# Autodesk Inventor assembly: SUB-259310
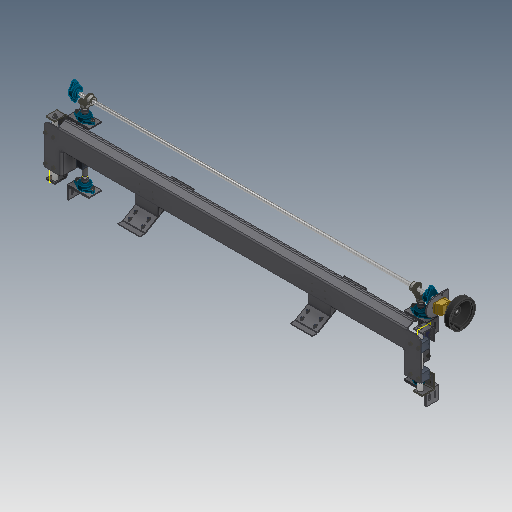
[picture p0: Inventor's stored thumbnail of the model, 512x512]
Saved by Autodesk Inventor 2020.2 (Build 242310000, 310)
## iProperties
Created: 2000-02
Part Number: SUB-259310
Document SubType Name: Assembly
Designer: sspink
Mass: 24162.7 g
Surface Area: 20552 cm^2
Volume: 6313.71 cm^3
Density: 3.82701 g/cm^3
Control State: 0
Checked Out: False
Master: False
Shininess: 0.0
Length Units: 11269
Angle Units: 11279
Time Units: 11290
Mass Units: 11283
Length Display Precision: 3
Angle Display Precision: 2
Compacted: True
Dimensions: 609,1x346,8x2359,6 mm
Mass: 24,163 kg
DocNumber: SUB-259310.iam
Folder: 01 - Themengebiete\Simplification\01 - Packaging machine\
VDS_Category: 3D Komponenten
Density: 0.0
Volumn: 0.0
Area: 0.0
PropertySet Name: Model Information
Author: sspink
Revision Number: -
Title: SUB-259310
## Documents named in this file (35)
- D:\07 - DEMODATEN\OTX 2019 - Dataset - UPDATE - Dez2019\Designs\07-Packing machine\SUB-259310.iam
- D:\07 - DEMODATEN\OTX 2019 - Dataset - UPDATE - Dez2019\Designs\07-Packing machine\Parts\ADSK-011691.ipt
- D:\07 - DEMODATEN\OTX 2019 - Dataset - UPDATE - Dez2019\Designs\07-Packing machine\Parts\ADSK-011692.ipt
- D:\07 - DEMODATEN\OTX 2019 - Dataset - UPDATE - Dez2019\Designs\07-Packing machine\Parts\ADSK-011325.ipt
- D:\07 - DEMODATEN\OTX 2019 - Dataset - UPDATE - Dez2019\Designs\07-Packing machine\Parts\ADSK-011690.ipt
- D:\07 - DEMODATEN\OTX 2019 - Dataset - UPDATE - Dez2019\Designs\07-Packing machine\Parts\ADSK-011695.ipt
- D:\07 - DEMODATEN\OTX 2019 - Dataset - UPDATE - Dez2019\Designs\07-Packing machine\Parts\ADSK-011694.ipt
- D:\07 - DEMODATEN\OTX 2019 - Dataset - UPDATE - Dez2019\Designs\07-Packing machine\500738.iam
- D:\07 - DEMODATEN\OTX 2019 - Dataset - UPDATE - Dez2019\Designs\07-Packing machine\Parts\ADSK-011697.ipt
- D:\07 - DEMODATEN\OTX 2019 - Dataset - UPDATE - Dez2019\Designs\07-Packing machine\500745.iam
- D:\07 - DEMODATEN\OTX 2019 - Dataset - UPDATE - Dez2019\Designs\07-Packing machine\Parts\ADSK-011714.ipt
- D:\07 - DEMODATEN\OTX 2019 - Dataset - UPDATE - Dez2019\Designs\07-Packing machine\Parts\ADSK-011700.ipt
- D:\07 - DEMODATEN\OTX 2019 - Dataset - UPDATE - Dez2019\Designs\07-Packing machine\Parts\ADSK-011716.ipt
- D:\07 - DEMODATEN\OTX 2019 - Dataset - UPDATE - Dez2019\Designs\07-Packing machine\Parts\ADSK-011702.ipt
- D:\07 - DEMODATEN\OTX 2019 - Dataset - UPDATE - Dez2019\Designs\07-Packing machine\Parts\ADSK-011309.ipt
- D:\07 - DEMODATEN\OTX 2019 - Dataset - UPDATE - Dez2019\Designs\07-Packing machine\Parts\ADSK-011704.ipt
- D:\07 - DEMODATEN\OTX 2019 - Dataset - UPDATE - Dez2019\Designs\07-Packing machine\Parts\ADSK-011768.ipt
- D:\07 - DEMODATEN\OTX 2019 - Dataset - UPDATE - Dez2019\Content Center Files\de-DE\DIN 125-1  B\DIN 125-1 - B 6,4.ipt
- D:\07 - DEMODATEN\OTX 2019 - Dataset - UPDATE - Dez2019\Content Center Files\de-DE\ISO 4032(1)\ISO 4032 - M6DIN EN.ipt
- D:\07 - DEMODATEN\OTX 2019 - Dataset - UPDATE - Dez2019\Content Center Files\de-DE\DIN 125-1  B\DIN 125-1 - B 5,3.ipt
- D:\07 - DEMODATEN\OTX 2019 - Dataset - UPDATE - Dez2019\Content Center Files\de-DE\ISO 4762(2)\ISO 4762 - M5 x 10ISO.ipt
- D:\07 - DEMODATEN\OTX 2019 - Dataset - UPDATE - Dez2019\Content Center Files\de-DE\DIN 125-1  B\DIN 125-1 - B 8,4.ipt
- D:\07 - DEMODATEN\OTX 2019 - Dataset - UPDATE - Dez2019\Content Center Files\de-DE\ISO 4032(1)\ISO 4032 - M8DIN EN.ipt
- D:\07 - DEMODATEN\OTX 2019 - Dataset - UPDATE - Dez2019\Content Center Files\de-DE\ISO 4762(2)\ISO 4762 - M8 x 55ISO.ipt
- D:\07 - DEMODATEN\OTX 2019 - Dataset - UPDATE - Dez2019\Content Center Files\de-DE\DIN 125-1  B\DIN 125-1 - B 10,5.ipt
- D:\07 - DEMODATEN\OTX 2019 - Dataset - UPDATE - Dez2019\Content Center Files\de-DE\ISO 4762(2)\ISO 4762 - M10 x 25ISO.ipt
- D:\07 - DEMODATEN\OTX 2019 - Dataset - UPDATE - Dez2019\Content Center Files\de-DE\ISO 4762(2)\ISO 4762 - M8 x 40ISO.ipt
- D:\07 - DEMODATEN\OTX 2019 - Dataset - UPDATE - Dez2019\Content Center Files\de-DE\ISO 2491 - A\ISO 2491 - A  5 x 3 x 16.ipt
- D:\07 - DEMODATEN\OTX 2019 - Dataset - UPDATE - Dez2019\Content Center Files\de-DE\ISO 4026\ISO 4026 - M5 x 6 - ISO.ipt
- D:\07 - DEMODATEN\OTX 2019 - Dataset - UPDATE - Dez2019\Content Center Files\de-DE\ISO 4026\ISO 4026 - M5 x 10 - ISO.ipt
- D:\07 - DEMODATEN\OTX 2019 - Dataset - UPDATE - Dez2019\Content Center Files\de-DE\ISO 4762(2)\ISO 4762 - M8 x 25ISO.ipt
- D:\07 - DEMODATEN\OTX 2019 - Dataset - UPDATE - Dez2019\Content Center Files\de-DE\ISO 4026\ISO 4026 - M5 x 8 - ISO.ipt
- D:\07 - DEMODATEN\OTX 2019 - Dataset - UPDATE - Dez2019\Designs\07-Packing machine\Parts\ADSK-014457.ipt
- D:\07 - DEMODATEN\OTX 2019 - Dataset - UPDATE - Dez2019\Content Center Files\de-DE\ISO 2491 - A\ISO 2491 - A  5 x 3 x 28.ipt
- D:\07 - DEMODATEN\OTX 2019 - Dataset - UPDATE - Dez2019\Content Center Files\de-DE\ISO 2491 - A\ISO 2491 - A  5 x 3 x 36.ipt
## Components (146 placed, 34 different names)
1. ADSK-011714:1 — Passend:163, Passend:164, Passend:170, Fluchtend:172, Passend:218
2. ADSK-011694:1 — Angle:2, Passend:45, Passend:46, Passend:47, Passend:48, Passend:49, Passend:50, Passend:107, Passend:108, Passend:109, Passend:110, Passend:111, Passend:112, Passend:113, Passend:114, Passend:115, Passend:116, Passend:117, Passend:118, Passend:135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
3. ADSK-011695:2 — Passend:45, Passend:48, Passend:49, Passend:51, Passend:53, Passend:54, Passend:55, Passend:68, Passend:70, Passend:72, Passend:74, Passend:76, Passend:78, Passend:80, Passend:82, Passend:84, Passend:86, Passend:88, Passend:90
4. ADSK-011695:1 — Passend:46, Passend:47, Passend:50, Passend:52, Passend:56, Passend:57, Passend:58, Passend:60, Passend:62, Passend:64, Passend:66
5. 500738:2 [sub-assembly] — Passend:51, Passend:53, Passend:54, Passend:55
6. 500738:1 [sub-assembly] — Passend:52, Passend:56, Passend:57, Passend:58
7. ADSK-011325:1 — Passend:113, Passend:114, Passend:115, Passend:123, Fluchtend:23, Passend:124, Passend:125
8. ADSK-011325:2 — Passend:116, Passend:117, Passend:118, Fluchtend:24
9. ADSK-011325:3 — Passend:110, Passend:111, Passend:112, Passend:121
10. ADSK-011325:4 — Passend:107, Passend:108, Passend:109, Passend:119, Passend:120
11. ADSK-011692:1 — Passend:125, Passend:126, Einfügen:50
12. ADSK-011692:2 — Passend:121, Passend:122, Einfügen:49
13. ADSK-011690:1 — Angle:2, Mate:25, Einfügen:49, Passend:134
14. ADSK-011690:2 — Passend:123, Fluchtend:23, Passend:124, Passend:126, Passend:130
15. ADSK-011691:1 — Einfügen:50, Fluchtend:24, Passend:128, Fluchtend:32
16. ADSK-011691:2 — Passend:119, Passend:120, Passend:122, Passend:132
17. ADSK-011697:1 — Passend:135, Passend:136, Passend:137, Passend:156, Drehung/Translation:1
18. ADSK-011714:2 — Mate:24, Mate:25, Passend:170, Passend:217
19. 500745:1 [sub-assembly] — Passend:147, Passend:148, Passend:162, Passend:225, Passend:226, Passend:233, Passend:234, Fluchtend:175, Passend:235, Tangential:6
20. ADSK-011700:1 — Mate:24, Mate:41, Mate:42, Passend:164, Fluchtend:34, Passend:166, Fluchtend:168, Passend:167, Passend:169, Tangential:2, Passend:221, Passend:222, Passend:224, Passend:227, Passend:229, Passend:236, Fluchtend:176, Passend:237, Passend:238, Passend:239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
21. ADSK-011714:4 — Passend:144, Passend:145, Passend:146, Passend:147, Passend:148, Passend:217
22. ADSK-011702:2 — Fluchtend:25, Fluchtend:26, Fluchtend:27, Passend:144, Passend:145, Passend:146
23. ADSK-011714:6 — Insert:12, Mate:39, Passend:142, Passend:143
24. ADSK-011702:4 — Insert:12, EINSTELLUNG, Passend:143, Fluchtend:25, Fluchtend:26, Fluchtend:27, Winkel:11, Fluchtend:31, Passend:157
25. ADSK-011716:2 — Mate:39, Passend:162
26. ADSK-011309:1 — Mate:44, Fluchtend:34, Passend:166, Fluchtend:168, Passend:177, Passend:178
27. ADSK-011768:1 — Mate:42, Mate:43, Angle:10, Mate:44, Fluchtend:173
28. ADSK-011704:1 — Mate:41, Mate:43, Angle:10, Fluchtend:32, Passend:163, Fluchtend:172, Fluchtend:173
29. ADSK-011697:2 — Passend:138, Passend:139, Passend:140, EINSTELLUNG, Passend:142
30. 500745:2 [sub-assembly] — Passend:156, Passend:161, Passend:220, Passend:223, Passend:228, Passend:231, Passend:232, Fluchtend:174, Tangential:4, Drehung/Translation:1
31. ADSK-011714:7
32. ADSK-011702:5 — Passend:218
33. ADSK-011714:8 — Passend:198, Passend:200
34. ADSK-011702:6 — Fluchtend:31, Passend:157
35. ADSK-011716:3 — Passend:161
36. Kegelrad1:3 — Passend:220, Passend:222, Passend:228, Passend:246, Passend:247, Drehung:1
37. Kegelrad1:4 — Passend:221, Passend:223, Fluchtend:176, Passend:243, Passend:245, Drehung:1
38. Kegelrad1:5 — Passend:226, Passend:227, Passend:235, Passend:252, Passend:254, Drehung:2
39. Kegelrad1:6 — Passend:224, Passend:225, Passend:236, Passend:249, Passend:251, Drehung:2
40. ISO 2491 A A  5 x 3 x 28:1 — Passend:231, Passend:232, Fluchtend:174, Passend:248
41. ISO 2491 A A  5 x 3 x 28:2 — Passend:233, Passend:234, Fluchtend:175, Passend:253
42. ISO 2491 A A  5 x 3 x 36:1 — Passend:237, Passend:238, Passend:239, Passend:244
43. ISO 2491 A A  5 x 3 x 36:2 — Passend:240, Passend:241, Passend:242, Passend:250
44. ISO 4026 M5 x 10:2 — Passend:246, Tangential:4
45. ISO 4026 M5 x 8:7 — Passend:247, Passend:248
46. ISO 4026 M5 x 10:3 — Passend:249, Passend:250
47. ISO 4026 M5 x 10:4 — Passend:251, Tangential:5
48. ISO 4026 M5 x 10:5 — Passend:252, Passend:253
49. ISO 4026 M5 x 10:6 — Passend:254, Tangential:6
50. ISO 4026 M5 x 10:1 — Passend:245, Tangential:3
51. ISO 4026 M5 x 8:6 — Passend:243, Passend:244
52. DIN 125-1 B B 8,4:13 — Passend:210, Passend:212
53. DIN 125-1 B B 8,4:14
54. DIN 125-1 B B 8,4:15 — Passend:214, Passend:216
55. DIN 125-1 B B 8,4:16
56. DIN 125-1 B B 8,4:17 — Passend:198, Passend:206, Passend:208
57. DIN 125-1 B B 8,4:18 — Passend:200
58. DIN 125-1 B B 8,4:19 — Passend:202, Passend:204
59. DIN 125-1 B B 8,4:20
60. ISO 4762 M8 x 25:1 — Passend:202
61. ISO 4762 M8 x 25:2 — Passend:204
62. ISO 4762 M8 x 25:3 — Passend:206
63. ISO 4762 M8 x 25:4 — Passend:208
64. ISO 4762 M8 x 25:5 — Passend:210
65. ISO 4762 M8 x 25:6 — Passend:212
66. ISO 4762 M8 x 25:7 — Passend:214
67. ISO 4762 M8 x 25:8 — Passend:216
68. ISO 2491 A A  5 x 3 x 16:1 — Passend:167, Passend:169, Passend:229, Passend:230
69. ISO 4026 M5 x 6:1 — Passend:178, Passend:230
70. ISO 4026 M5 x 6:2 — Passend:177, Tangential:2
71. DIN 125-1 B B 10,5:1 — Passend:128
72. DIN 125-1 B B 10,5:2 — Passend:130
73. DIN 125-1 B B 10,5:3 — Passend:132
74. DIN 125-1 B B 10,5:4 — Passend:134
75. ISO 4762 M10 x 25:1
76. ISO 4762 M10 x 25:2
77. ISO 4762 M10 x 25:3
78. ISO 4762 M10 x 25:4
79. DIN 125-1 B B 8,4:9
80. DIN 125-1 B B 8,4:10
81. DIN 125-1 B B 8,4:11
82. DIN 125-1 B B 8,4:12
83. DIN EN 24032 M8:9
84. DIN EN 24032 M8:10
85. DIN EN 24032 M8:11
86. DIN EN 24032 M8:12
87. ISO 4762 M8 x 40:1
88. ISO 4762 M8 x 40:2
89. ISO 4762 M8 x 40:3
90. ISO 4762 M8 x 40:4
91. DIN 125-1 B B 8,4:1
92. DIN 125-1 B B 8,4:2
93. DIN 125-1 B B 8,4:3
94. DIN 125-1 B B 8,4:4
95. DIN 125-1 B B 8,4:5
96. DIN 125-1 B B 8,4:6
97. DIN 125-1 B B 8,4:7
98. DIN 125-1 B B 8,4:8
99. DIN EN 24032 M8:1
100. DIN EN 24032 M8:2
101. DIN EN 24032 M8:3
102. DIN EN 24032 M8:4
103. DIN EN 24032 M8:5
104. DIN EN 24032 M8:6
105. DIN EN 24032 M8:7
106. DIN EN 24032 M8:8
107. ISO 4762 M8 x 55:1
108. ISO 4762 M8 x 55:2
109. ISO 4762 M8 x 55:3
110. ISO 4762 M8 x 55:4
111. ISO 4762 M8 x 55:5
112. ISO 4762 M8 x 55:6
113. ISO 4762 M8 x 55:7
114. ISO 4762 M8 x 55:8
115. DIN 125-1 B B 6,4:1 — Passend:60
116. DIN 125-1 B B 6,4:2 — Passend:62
117. DIN 125-1 B B 6,4:3 — Passend:64
118. DIN 125-1 B B 6,4:4 — Passend:66
119. DIN EN 24032 M6:1
120. DIN EN 24032 M6:2
121. DIN EN 24032 M6:3
122. DIN EN 24032 M6:4
123. DIN 125-1 B B 6,4:5 — Passend:68
124. DIN 125-1 B B 6,4:6 — Passend:70
125. DIN 125-1 B B 6,4:7 — Passend:72
126. DIN 125-1 B B 6,4:8 — Passend:74
127. DIN EN 24032 M6:5
128. DIN EN 24032 M6:6
129. DIN EN 24032 M6:7
130. DIN EN 24032 M6:8
131. DIN 125-1 B B 5,3:1 — Passend:76
132. DIN 125-1 B B 5,3:2 — Passend:78
133. DIN 125-1 B B 5,3:3 — Passend:80
134. DIN 125-1 B B 5,3:4 — Passend:82, Passend:92, Passend:94, Passend:96, Passend:98, Passend:100, Passend:102, Passend:104, Passend:106
135. DIN 125-1 B B 5,3:5 — Passend:84
136. DIN 125-1 B B 5,3:6 — Passend:86
137. DIN 125-1 B B 5,3:7 — Passend:88
138. DIN 125-1 B B 5,3:8 — Passend:90
139. ISO 4762 M5 x 10:1 — Passend:92
140. ISO 4762 M5 x 10:2 — Passend:94
141. ISO 4762 M5 x 10:3 — Passend:96
142. ISO 4762 M5 x 10:4 — Passend:98
143. ISO 4762 M5 x 10:5 — Passend:100
144. ISO 4762 M5 x 10:6 — Passend:102
145. ISO 4762 M5 x 10:7 — Passend:104
146. ISO 4762 M5 x 10:8 — Passend:106
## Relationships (170: Mate 142, Flush 14, Tangent 5, Angle 3, Insert 3, RelateRotation 2, RelateRotateTranslate 1)
- EINSTELLUNG [Mate]: ADSK-011702:4 ↔ ADSK-011697:2
- Drehung/Translation:1 [RelateRotateTranslate]: ADSK-011697:1 ↔ 500745:2
- Angle:2: ADSK-011694:1 ↔ ADSK-011690:1
- Mate:24: ADSK-011714:2 ↔ ADSK-011700:1
- Mate:25: ADSK-011690:1 ↔ ADSK-011714:2
- Insert:12: ADSK-011714:6 ↔ ADSK-011702:4
- Mate:39: ADSK-011714:6 ↔ ADSK-011716:2
- Mate:41: ADSK-011700:1 ↔ ADSK-011704:1
- Mate:42: ADSK-011700:1 ↔ ADSK-011768:1
- Mate:43: ADSK-011768:1 ↔ ADSK-011704:1
- Angle:10: ADSK-011768:1 ↔ ADSK-011704:1
- Mate:44: ADSK-011309:1 ↔ ADSK-011768:1
- Passend:45 [Mate]: ADSK-011694:1 ↔ ADSK-011695:2
- Passend:46 [Mate]: ADSK-011694:1 ↔ ADSK-011695:1
- Passend:47 [Mate]: ADSK-011694:1 ↔ ADSK-011695:1
- Passend:48 [Mate]: ADSK-011694:1 ↔ ADSK-011695:2
- Passend:49 [Mate]: ADSK-011694:1 ↔ ADSK-011695:2
- Passend:50 [Mate]: ADSK-011694:1 ↔ ADSK-011695:1
- Passend:51 [Mate]: ADSK-011695:2 ↔ 500738:2
- Passend:52 [Mate]: ADSK-011695:1 ↔ 500738:1
- Passend:53 [Mate]: ADSK-011695:2 ↔ 500738:2
- Passend:54 [Mate]: ADSK-011695:2 ↔ 500738:2
- Passend:55 [Mate]: ADSK-011695:2 ↔ 500738:2
- Passend:56 [Mate]: ADSK-011695:1 ↔ 500738:1
- Passend:57 [Mate]: ADSK-011695:1 ↔ 500738:1
- Passend:58 [Mate]: ADSK-011695:1 ↔ 500738:1
- Passend:60 [Mate]: ADSK-011695:1 ↔ DIN 125-1 B B 6,4:1
- Passend:62 [Mate]: ADSK-011695:1 ↔ DIN 125-1 B B 6,4:2
- Passend:64 [Mate]: ADSK-011695:1 ↔ DIN 125-1 B B 6,4:3
- Passend:66 [Mate]: ADSK-011695:1 ↔ DIN 125-1 B B 6,4:4
- Passend:68 [Mate]: ADSK-011695:2 ↔ DIN 125-1 B B 6,4:5
- Passend:70 [Mate]: ADSK-011695:2 ↔ DIN 125-1 B B 6,4:6
- Passend:72 [Mate]: ADSK-011695:2 ↔ DIN 125-1 B B 6,4:7
- Passend:74 [Mate]: ADSK-011695:2 ↔ DIN 125-1 B B 6,4:8
- Passend:76 [Mate]: ADSK-011695:2 ↔ DIN 125-1 B B 5,3:1
- Passend:78 [Mate]: ADSK-011695:2 ↔ DIN 125-1 B B 5,3:2
- Passend:80 [Mate]: ADSK-011695:2 ↔ DIN 125-1 B B 5,3:3
- Passend:82 [Mate]: ADSK-011695:2 ↔ DIN 125-1 B B 5,3:4
- Passend:84 [Mate]: ADSK-011695:2 ↔ DIN 125-1 B B 5,3:5
- Passend:86 [Mate]: ADSK-011695:2 ↔ DIN 125-1 B B 5,3:6
- Passend:88 [Mate]: ADSK-011695:2 ↔ DIN 125-1 B B 5,3:7
- Passend:90 [Mate]: ADSK-011695:2 ↔ DIN 125-1 B B 5,3:8
- Passend:92 [Mate]: DIN 125-1 B B 5,3:4 ↔ ISO 4762 M5 x 10:1
- Passend:94 [Mate]: DIN 125-1 B B 5,3:4 ↔ ISO 4762 M5 x 10:2
- Passend:96 [Mate]: DIN 125-1 B B 5,3:4 ↔ ISO 4762 M5 x 10:3
- Passend:98 [Mate]: DIN 125-1 B B 5,3:4 ↔ ISO 4762 M5 x 10:4
- Passend:100 [Mate]: DIN 125-1 B B 5,3:4 ↔ ISO 4762 M5 x 10:5
- Passend:102 [Mate]: DIN 125-1 B B 5,3:4 ↔ ISO 4762 M5 x 10:6
- Passend:104 [Mate]: DIN 125-1 B B 5,3:4 ↔ ISO 4762 M5 x 10:7
- Passend:106 [Mate]: DIN 125-1 B B 5,3:4 ↔ ISO 4762 M5 x 10:8
- Passend:107 [Mate]: ADSK-011694:1 ↔ ADSK-011325:4
- Passend:108 [Mate]: ADSK-011694:1 ↔ ADSK-011325:4
- Passend:109 [Mate]: ADSK-011694:1 ↔ ADSK-011325:4
- Passend:110 [Mate]: ADSK-011694:1 ↔ ADSK-011325:3
- Passend:111 [Mate]: ADSK-011694:1 ↔ ADSK-011325:3
- Passend:112 [Mate]: ADSK-011694:1 ↔ ADSK-011325:3
- Passend:113 [Mate]: ADSK-011694:1 ↔ ADSK-011325:1
- Passend:114 [Mate]: ADSK-011694:1 ↔ ADSK-011325:1
- Passend:115 [Mate]: ADSK-011694:1 ↔ ADSK-011325:1
- Passend:116 [Mate]: ADSK-011694:1 ↔ ADSK-011325:2
- Passend:117 [Mate]: ADSK-011694:1 ↔ ADSK-011325:2
- Passend:118 [Mate]: ADSK-011694:1 ↔ ADSK-011325:2
- Passend:119 [Mate]: ADSK-011325:4 ↔ ADSK-011691:2
- Passend:120 [Mate]: ADSK-011325:4 ↔ ADSK-011691:2
- Passend:121 [Mate]: ADSK-011325:3 ↔ ADSK-011692:2
- Passend:122 [Mate]: ADSK-011692:2 ↔ ADSK-011691:2
- Einfügen:49 [Insert]: ADSK-011692:2 ↔ ADSK-011690:1
- Passend:123 [Mate]: ADSK-011325:1 ↔ ADSK-011690:2
- Fluchtend:23 [Flush]: ADSK-011325:1 ↔ ADSK-011690:2
- Passend:124 [Mate]: ADSK-011325:1 ↔ ADSK-011690:2
- Passend:125 [Mate]: ADSK-011325:1 ↔ ADSK-011692:1
- Passend:126 [Mate]: ADSK-011692:1 ↔ ADSK-011690:2
- Einfügen:50 [Insert]: ADSK-011692:1 ↔ ADSK-011691:1
- Fluchtend:24 [Flush]: ADSK-011325:2 ↔ ADSK-011691:1
- Passend:128 [Mate]: ADSK-011691:1 ↔ DIN 125-1 B B 10,5:1
- Passend:130 [Mate]: ADSK-011690:2 ↔ DIN 125-1 B B 10,5:2
- Passend:132 [Mate]: ADSK-011691:2 ↔ DIN 125-1 B B 10,5:3
- Passend:134 [Mate]: ADSK-011690:1 ↔ DIN 125-1 B B 10,5:4
- Passend:135 [Mate]: ADSK-011694:1 ↔ ADSK-011697:1
- Passend:136 [Mate]: ADSK-011694:1 ↔ ADSK-011697:1
- Passend:137 [Mate]: ADSK-011694:1 ↔ ADSK-011697:1
- Passend:138 [Mate]: ADSK-011694:1 ↔ ADSK-011697:2
- Passend:139 [Mate]: ADSK-011694:1 ↔ ADSK-011697:2
- Passend:140 [Mate]: ADSK-011694:1 ↔ ADSK-011697:2
- Passend:142 [Mate]: ADSK-011714:6 ↔ ADSK-011697:2
- Passend:143 [Mate]: ADSK-011714:6 ↔ ADSK-011702:4
- Fluchtend:25 [Flush]: ADSK-011702:2 ↔ ADSK-011702:4
- Fluchtend:26 [Flush]: ADSK-011702:2 ↔ ADSK-011702:4
- Fluchtend:27 [Flush]: ADSK-011702:2 ↔ ADSK-011702:4
- Winkel:11 [Angle]: ADSK-011694:1 ↔ ADSK-011702:4
- Passend:144 [Mate]: ADSK-011714:4 ↔ ADSK-011702:2
- Passend:145 [Mate]: ADSK-011714:4 ↔ ADSK-011702:2
- Passend:146 [Mate]: ADSK-011714:4 ↔ ADSK-011702:2
- Passend:147 [Mate]: 500745:1 ↔ ADSK-011714:4
- Passend:148 [Mate]: 500745:1 ↔ ADSK-011714:4
- Passend:156 [Mate]: ADSK-011697:1 ↔ 500745:2
- Fluchtend:31 [Flush]: ADSK-011702:4 ↔ ADSK-011702:6
- Passend:157 [Mate]: ADSK-011702:4 ↔ ADSK-011702:6
- Fluchtend:32 [Flush]: ADSK-011691:1 ↔ ADSK-011704:1
- Passend:161 [Mate]: 500745:2 ↔ ADSK-011716:3
- Passend:162 [Mate]: 500745:1 ↔ ADSK-011716:2
- Passend:163 [Mate]: ADSK-011714:1 ↔ ADSK-011704:1
- Passend:164 [Mate]: ADSK-011714:1 ↔ ADSK-011700:1
- Fluchtend:34 [Flush]: ADSK-011700:1 ↔ ADSK-011309:1
- Passend:166 [Mate]: ADSK-011700:1 ↔ ADSK-011309:1
- Fluchtend:168 [Flush]: ADSK-011700:1 ↔ ADSK-011309:1
- Passend:167 [Mate]: ADSK-011700:1 ↔ ISO 2491 A A  5 x 3 x 16:1
- Passend:169 [Mate]: ADSK-011700:1 ↔ ISO 2491 A A  5 x 3 x 16:1
- Passend:170 [Mate]: ADSK-011714:1 ↔ ADSK-011714:2
- Passend:177 [Mate]: ADSK-011309:1 ↔ ISO 4026 M5 x 6:2
- Passend:178 [Mate]: ADSK-011309:1 ↔ ISO 4026 M5 x 6:1
- Tangential:2: ADSK-011700:1 ↔ ISO 4026 M5 x 6:2
- Passend:198 [Mate]: ADSK-011714:8 ↔ DIN 125-1 B B 8,4:17
- Passend:200 [Mate]: ADSK-011714:8 ↔ DIN 125-1 B B 8,4:18
- Passend:202 [Mate]: DIN 125-1 B B 8,4:19 ↔ ISO 4762 M8 x 25:1
- Passend:204 [Mate]: DIN 125-1 B B 8,4:19 ↔ ISO 4762 M8 x 25:2
- Passend:206 [Mate]: DIN 125-1 B B 8,4:17 ↔ ISO 4762 M8 x 25:3
- Passend:208 [Mate]: DIN 125-1 B B 8,4:17 ↔ ISO 4762 M8 x 25:4
- Passend:210 [Mate]: DIN 125-1 B B 8,4:13 ↔ ISO 4762 M8 x 25:5
- Passend:212 [Mate]: DIN 125-1 B B 8,4:13 ↔ ISO 4762 M8 x 25:6
- Passend:214 [Mate]: DIN 125-1 B B 8,4:15 ↔ ISO 4762 M8 x 25:7
- Passend:216 [Mate]: DIN 125-1 B B 8,4:15 ↔ ISO 4762 M8 x 25:8
- Fluchtend:172 [Flush]: ADSK-011714:1 ↔ ADSK-011704:1
- Passend:217 [Mate]: ADSK-011714:2 ↔ ADSK-011714:4
- Fluchtend:173 [Flush]: ADSK-011768:1 ↔ ADSK-011704:1
- Passend:218 [Mate]: ADSK-011714:1 ↔ ADSK-011702:5
- Passend:220 [Mate]: 500745:2 ↔ Kegelrad1:3
- Passend:221 [Mate]: ADSK-011700:1 ↔ Kegelrad1:4
- Passend:222 [Mate]: ADSK-011700:1 ↔ Kegelrad1:3
- Passend:223 [Mate]: 500745:2 ↔ Kegelrad1:4
- Passend:224 [Mate]: ADSK-011700:1 ↔ Kegelrad1:6
- Passend:225 [Mate]: 500745:1 ↔ Kegelrad1:6
- Passend:226 [Mate]: 500745:1 ↔ Kegelrad1:5
- Passend:227 [Mate]: ADSK-011700:1 ↔ Kegelrad1:5
- Passend:228 [Mate]: 500745:2 ↔ Kegelrad1:3
- Passend:229 [Mate]: ADSK-011700:1 ↔ ISO 2491 A A  5 x 3 x 16:1
- Passend:230 [Mate]: ISO 2491 A A  5 x 3 x 16:1 ↔ ISO 4026 M5 x 6:1
- Passend:231 [Mate]: 500745:2 ↔ ISO 2491 A A  5 x 3 x 28:1
- Passend:232 [Mate]: 500745:2 ↔ ISO 2491 A A  5 x 3 x 28:1
- Fluchtend:174 [Flush]: 500745:2 ↔ ISO 2491 A A  5 x 3 x 28:1
- Passend:233 [Mate]: 500745:1 ↔ ISO 2491 A A  5 x 3 x 28:2
- Passend:234 [Mate]: 500745:1 ↔ ISO 2491 A A  5 x 3 x 28:2
- Fluchtend:175 [Flush]: 500745:1 ↔ ISO 2491 A A  5 x 3 x 28:2
- Passend:235 [Mate]: 500745:1 ↔ Kegelrad1:5
- Passend:236 [Mate]: ADSK-011700:1 ↔ Kegelrad1:6
- Fluchtend:176 [Flush]: ADSK-011700:1 ↔ Kegelrad1:4
- Passend:237 [Mate]: ADSK-011700:1 ↔ ISO 2491 A A  5 x 3 x 36:1
- Passend:238 [Mate]: ADSK-011700:1 ↔ ISO 2491 A A  5 x 3 x 36:1
- Passend:239 [Mate]: ADSK-011700:1 ↔ ISO 2491 A A  5 x 3 x 36:1
- Passend:240 [Mate]: ADSK-011700:1 ↔ ISO 2491 A A  5 x 3 x 36:2
- Passend:241 [Mate]: ADSK-011700:1 ↔ ISO 2491 A A  5 x 3 x 36:2
- Passend:242 [Mate]: ADSK-011700:1 ↔ ISO 2491 A A  5 x 3 x 36:2
- Passend:243 [Mate]: Kegelrad1:4 ↔ ISO 4026 M5 x 8:6
- Passend:244 [Mate]: ISO 2491 A A  5 x 3 x 36:1 ↔ ISO 4026 M5 x 8:6
- Passend:245 [Mate]: Kegelrad1:4 ↔ ISO 4026 M5 x 10:1
- Tangential:3: ADSK-011700:1 ↔ ISO 4026 M5 x 10:1
- Passend:246 [Mate]: Kegelrad1:3 ↔ ISO 4026 M5 x 10:2
- Tangential:4: 500745:2 ↔ ISO 4026 M5 x 10:2
- Passend:247 [Mate]: Kegelrad1:3 ↔ ISO 4026 M5 x 8:7
- Passend:248 [Mate]: ISO 2491 A A  5 x 3 x 28:1 ↔ ISO 4026 M5 x 8:7
- Passend:249 [Mate]: Kegelrad1:6 ↔ ISO 4026 M5 x 10:3
- Passend:250 [Mate]: ISO 2491 A A  5 x 3 x 36:2 ↔ ISO 4026 M5 x 10:3
- Passend:251 [Mate]: Kegelrad1:6 ↔ ISO 4026 M5 x 10:4
- Tangential:5: ADSK-011700:1 ↔ ISO 4026 M5 x 10:4
- Passend:252 [Mate]: Kegelrad1:5 ↔ ISO 4026 M5 x 10:5
- Passend:253 [Mate]: ISO 2491 A A  5 x 3 x 28:2 ↔ ISO 4026 M5 x 10:5
- Passend:254 [Mate]: Kegelrad1:5 ↔ ISO 4026 M5 x 10:6
- Tangential:6: 500745:1 ↔ ISO 4026 M5 x 10:6
- Drehung:1 [RelateRotation]: Kegelrad1:3 ↔ Kegelrad1:4
- Drehung:2 [RelateRotation]: Kegelrad1:5 ↔ Kegelrad1:6
## Named parameters: d305_d303 = 0, d306_d304 = 0, d307_d294 = 0, d308_d118 = 0, d309_d129 = 0, d310_d296 = 0, d311_d297 = 0, d312_d298 = 342 mm, d313_d300 = 0, d314_d301 = 0, d315_d302 = 0
